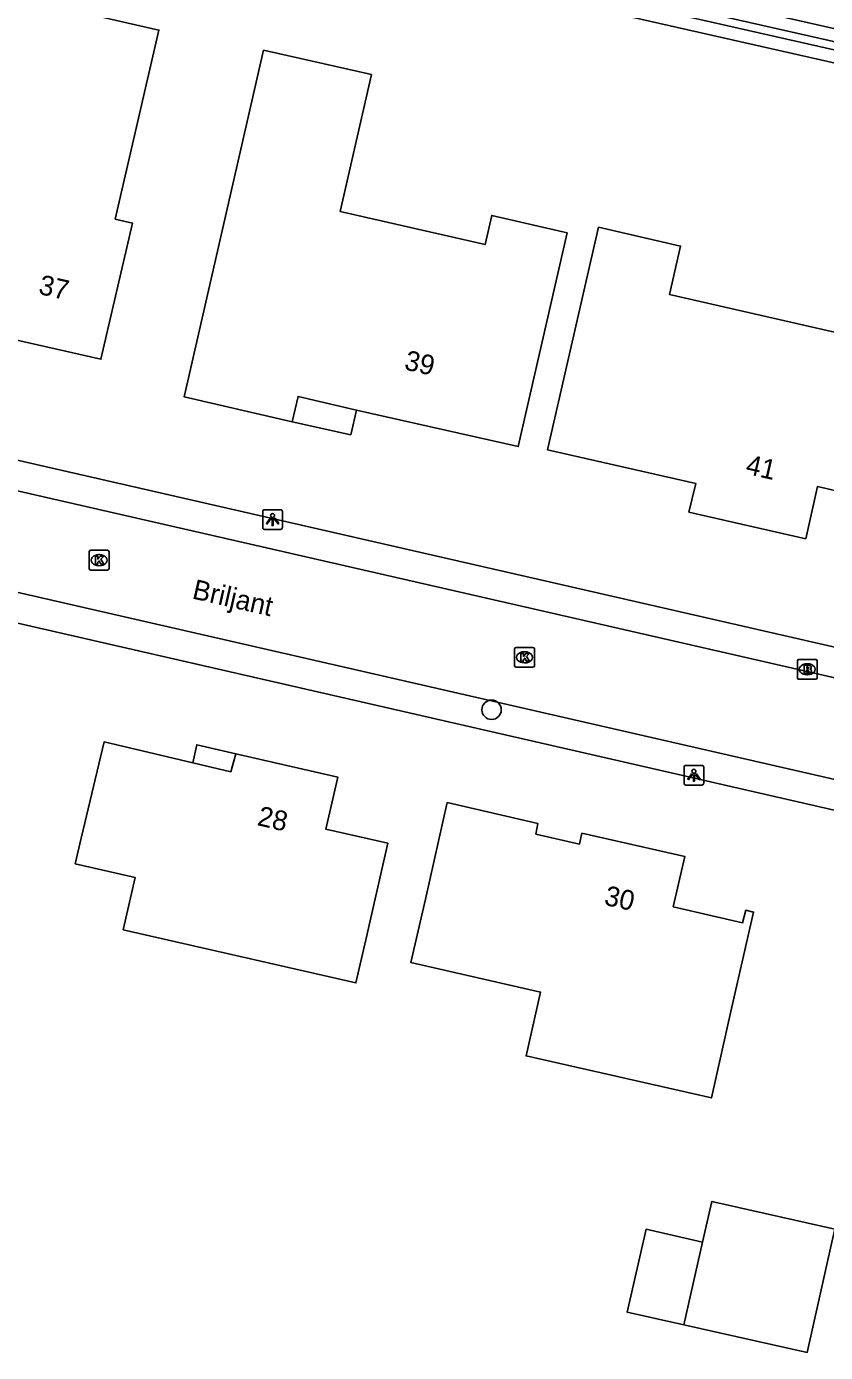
# Model space of a CAD drawing. Extents: x 159628 to 160723, y 388176 to 389416.
# Drawn here: x 160277.9 to 160318.3, y 388744.4 to 388811.4 of the extents above; entities that cross this region are included whole.
import ezdxf

# ---------------------------------------------------------------- set-up
doc = ezdxf.new("R2010")
doc.units = 0
for name, color, linetype in [('IMGEO_Boom', 7, 'Continuous'), ('IMGEO_Brandkraan', 7, 'Continuous'), ('IMGEO_Erf', 7, 'Continuous'), ('IMGEO_Groenvoorziening', 7, 'Continuous'), ('IMGEO_Kolk', 7, 'Continuous'), ('IMGEO_Lichtpunt', 7, 'Continuous'), ('IMGEO_Openbare_ruimte_label', 7, 'Continuous'), ('IMGEO_Pand', 7, 'Continuous'), ('IMGEO_Pand_nummerreeks', 7, 'Continuous'), ('IMGEO_Pand_overbouw', 7, 'Continuous'), ('IMGEO_Rijbaan_lokaal_open', 7, 'Continuous'), ('IMGEO_Voetpad_open', 7, 'Continuous'), ('IMGEO_Waterloop', 7, 'Continuous')]:
    doc.layers.add(name, color=color, linetype=linetype)

msp = doc.modelspace()

# ---------------------------------------------------------------- linework, layer by layer
at = {"layer": 'IMGEO_Boom'}
msp.add_circle((160301.407, 388776.893), 0.489, dxfattribs=at)
at = {"layer": 'IMGEO_Brandkraan'}
for p, q in [((160316.845, 388778.511), (160316.845, 388779.363)), ((160316.92, 388779.437), (160317.772, 388779.437)), ((160317.333, 388779.217), (160317.358, 388779.217)), ((160317.846, 388779.363), (160317.846, 388778.511)), ((160317.356, 388778.657), (160317.331, 388778.657)), ((160317.772, 388778.437), (160316.92, 388778.437))]:
    msp.add_line(p, q, dxfattribs=at)
for points in [[(160316.845, 388778.511), (160316.845, 388779.363)], [(160316.92, 388779.437), (160317.772, 388779.437)], [(160317.846, 388779.363), (160317.846, 388778.511)], [(160317.193, 388779.137), (160317.193, 388778.737), (160317.406, 388778.737)], [(160317.424, 388779.137), (160317.193, 388779.137)], [(160317.372, 388779.056), (160317.318, 388779.056), (160317.318, 388778.98)], [(160317.318, 388778.98), (160317.371, 388778.98)], [(160317.38, 388778.904), (160317.318, 388778.904), (160317.318, 388778.823)], [(160317.318, 388778.823), (160317.38, 388778.823)], [(160317.772, 388778.437), (160316.92, 388778.437)]]:
    msp.add_lwpolyline(points, dxfattribs=at)
for centre, radius, start, end in [((160316.922, 388779.361), 0.0765, 91.55205, 178.44795), ((160316.922, 388779.361), 0.0765, 91.55205, 178.44795), ((160317.77, 388779.361), 0.0765, 1.55205, 88.44795), ((160317.77, 388779.361), 0.0765, 1.55205, 88.44795), ((160316.922, 388778.513), 0.0765, 181.55205, 268.44795), ((160316.922, 388778.513), 0.0765, 181.55205, 268.44795), ((160317.373, 388779.018), 0.0379, 267.82845, 90.93552), ((160317.381, 388778.863), 0.0404, 269.87594, 90.50774), ((160317.412, 388778.988), 0.251, 268.66757, 293.53466), ((160317.428, 388778.992), 0.145, 59.4692, 91.53667), ((160317.453, 388779.039), 0.0922, 285.51372, 58.15012), ((160317.458, 388778.847), 0.105, 301.31148, 78.98903), ((160317.77, 388778.513), 0.0765, 271.55205, 358.44795), ((160317.77, 388778.513), 0.0765, 271.55205, 358.44795)]:
    msp.add_arc(centre, radius, start, end, dxfattribs=at)
for centre, major_axis, ratio, start_param, end_param in [((160317.332, 388778.937), (-0.387, 0.002), 0.722429, 4.712389, 7.853982), ((160317.357, 388778.937), (-0.39, 0.002), 0.717154, 1.570796, 4.712389)]:
    msp.add_ellipse(centre, major_axis=major_axis, ratio=ratio, start_param=start_param, end_param=end_param, dxfattribs=at)
at = {"layer": 'IMGEO_Erf'}
msp.add_lwpolyline([(160184.451, 388841.51), (160190.942, 388838.493), (160275.805, 388819.285), (160345.403, 388803.532)], dxfattribs=at)
at = {"layer": 'IMGEO_Groenvoorziening'}
msp.add_lwpolyline([(160345.403, 388803.532), (160345.702, 388804.941), (160343.204, 388805.76), (160276.177, 388820.926), (160191.577, 388840.068), (160187.273, 388842.53), (160192.324, 388844.405), (160277.11, 388825.048), (160331.448, 388812.643), (160346.394, 388809.56)], dxfattribs=at)
at = {"layer": 'IMGEO_Kolk'}
for p, q in [((160281.091, 388784.022), (160281.091, 388784.874)), ((160281.166, 388784.948), (160282.018, 388784.948)), ((160281.579, 388784.728), (160281.604, 388784.728)), ((160282.092, 388784.874), (160282.092, 388784.022)), ((160282.018, 388783.948), (160281.166, 388783.948)), ((160281.602, 388784.168), (160281.577, 388784.168)), ((160302.571, 388779.116), (160302.571, 388779.968)), ((160302.646, 388780.042), (160303.498, 388780.042)), ((160303.572, 388779.968), (160303.572, 388779.116)), ((160303.082, 388779.262), (160303.057, 388779.262)), ((160303.059, 388779.822), (160303.084, 388779.822)), ((160303.498, 388779.042), (160302.646, 388779.042))]:
    msp.add_line(p, q, dxfattribs=at)
for points in [[(160281.091, 388784.022), (160281.091, 388784.874)], [(160281.166, 388784.948), (160282.018, 388784.948)], [(160281.412, 388784.648), (160281.535, 388784.648), (160281.535, 388784.497), (160281.665, 388784.648), (160281.829, 388784.648), (160281.683, 388784.497), (160281.836, 388784.248), (160281.684, 388784.248), (160281.599, 388784.412), (160281.535, 388784.345), (160281.535, 388784.248), (160281.412, 388784.248), (160281.412, 388784.648)], [(160282.092, 388784.874), (160282.092, 388784.022)], [(160282.018, 388783.948), (160281.166, 388783.948)], [(160302.571, 388779.116), (160302.571, 388779.968)], [(160302.646, 388780.042), (160303.498, 388780.042)], [(160303.572, 388779.968), (160303.572, 388779.116)], [(160302.892, 388779.742), (160303.015, 388779.742), (160303.015, 388779.591), (160303.145, 388779.742), (160303.309, 388779.742), (160303.163, 388779.591), (160303.316, 388779.342), (160303.164, 388779.342), (160303.079, 388779.506), (160303.015, 388779.439), (160303.015, 388779.342), (160302.892, 388779.342), (160302.892, 388779.742)], [(160303.498, 388779.042), (160302.646, 388779.042)]]:
    msp.add_lwpolyline(points, dxfattribs=at)
for centre, start, end in [((160281.168, 388784.872), 91.55205, 178.44795), ((160281.168, 388784.872), 91.55205, 178.44795), ((160282.016, 388784.872), 1.55205, 88.44795), ((160282.016, 388784.872), 1.55205, 88.44795), ((160281.168, 388784.024), 181.55205, 268.44795), ((160281.168, 388784.024), 181.55205, 268.44795), ((160282.016, 388784.024), 271.55205, 358.44795), ((160282.016, 388784.024), 271.55205, 358.44795), ((160302.648, 388779.966), 91.55205, 178.44795), ((160302.648, 388779.966), 91.55205, 178.44795), ((160303.496, 388779.966), 1.55205, 88.44795), ((160303.496, 388779.966), 1.55205, 88.44795), ((160302.648, 388779.118), 181.55205, 268.44795), ((160302.648, 388779.118), 181.55205, 268.44795), ((160303.496, 388779.118), 271.55205, 358.44795), ((160303.496, 388779.118), 271.55205, 358.44795)]:
    msp.add_arc(centre, 0.0765, start, end, dxfattribs=at)
for centre, major_axis, ratio, start_param, end_param in [((160281.578, 388784.448), (-0.387, 0.002), 0.722429, 4.712389, 7.853982), ((160281.603, 388784.448), (-0.39, 0.002), 0.717154, 1.570796, 4.712389), ((160303.058, 388779.542), (-0.387, 0.002), 0.722429, 4.712389, 7.853982), ((160303.083, 388779.542), (-0.39, 0.002), 0.717154, 1.570796, 4.712389)]:
    msp.add_ellipse(centre, major_axis=major_axis, ratio=ratio, start_param=start_param, end_param=end_param, dxfattribs=at)
at = {"layer": 'IMGEO_Lichtpunt'}
for p, q in [((160289.852, 388786.904), (160289.852, 388786.097)), ((160289.852, 388786.904), (160289.852, 388786.097)), ((160290.754, 388786.999), (160289.946, 388786.999)), ((160290.754, 388786.999), (160289.946, 388786.999)), ((160290.848, 388786.097), (160290.848, 388786.904)), ((160290.848, 388786.097), (160290.848, 388786.904)), ((160289.946, 388786.003), (160290.754, 388786.003)), ((160289.946, 388786.003), (160290.754, 388786.003)), ((160311.123, 388773.987), (160311.123, 388773.18)), ((160311.123, 388773.987), (160311.123, 388773.18)), ((160312.025, 388774.082), (160311.217, 388774.082)), ((160312.025, 388774.082), (160311.217, 388774.082)), ((160312.119, 388773.18), (160312.119, 388773.987)), ((160312.119, 388773.18), (160312.119, 388773.987)), ((160311.217, 388773.086), (160312.025, 388773.086)), ((160311.217, 388773.086), (160312.025, 388773.086))]:
    msp.add_line(p, q, dxfattribs=at)
for points in [[(160290.226, 388786.568), (160290.265, 388786.54), (160290.077, 388786.278), (160290.039, 388786.305), (160290.226, 388786.568)], [(160290.438, 388786.54), (160290.476, 388786.567), (160290.663, 388786.305), (160290.624, 388786.277), (160290.438, 388786.54)], [(160290.328, 388786.52), (160290.375, 388786.52), (160290.375, 388786.198), (160290.328, 388786.198), (160290.328, 388786.52)], [(160311.497, 388773.651), (160311.536, 388773.623), (160311.348, 388773.361), (160311.31, 388773.388), (160311.497, 388773.651)], [(160311.599, 388773.603), (160311.646, 388773.603), (160311.646, 388773.281), (160311.599, 388773.281), (160311.599, 388773.603)], [(160311.709, 388773.623), (160311.747, 388773.65), (160311.934, 388773.388), (160311.895, 388773.36), (160311.709, 388773.623)]]:
    msp.add_lwpolyline(points, dxfattribs=at)
for centre in [(160290.351, 388786.702), (160311.622, 388773.785)]:
    msp.add_circle(centre, 0.0994, dxfattribs=at)
for centre, start, end in [((160289.946, 388786.904), 90, 180), ((160289.946, 388786.904), 90, 180), ((160290.754, 388786.904), 0, 90), ((160290.754, 388786.904), 0, 90), ((160289.946, 388786.097), 180, 270), ((160289.946, 388786.097), 180, 270), ((160290.754, 388786.097), 270, 0), ((160290.754, 388786.097), 270, 360), ((160311.217, 388773.987), 90, 180), ((160311.217, 388773.987), 90, 180), ((160312.025, 388773.987), 0, 90), ((160312.025, 388773.987), 0, 90), ((160311.217, 388773.18), 180, 270), ((160311.217, 388773.18), 180, 270), ((160312.025, 388773.18), 270, 0), ((160312.025, 388773.18), 270, 360)]:
    msp.add_arc(centre, 0.0946, start, end, dxfattribs=at)
at = {"layer": 'IMGEO_Pand'}
for points in [[(160269.416, 388805.915), (160275.66, 388804.469), (160277.599, 388812.844), (160284.612, 388811.221), (160282.403, 388801.679), (160283.279, 388801.476), (160281.686, 388794.597), (160275.782, 388795.937), (160275.862, 388796.301), (160274.298, 388796.665), (160274.011, 388795.415), (160272.055, 388795.867), (160271.994, 388795.641), (160270.709, 388795.976), (160270.739, 388796.156), (160268.289, 388796.758), (160269.045, 388800.332), (160268.176, 388800.561), (160269.416, 388805.915)], [(160289.9, 388810.21), (160295.34, 388808.98), (160293.762, 388802.068), (160301.084, 388800.397), (160301.418, 388801.859), (160305.22, 388800.991), (160302.753, 388790.184), (160294.594, 388792.025), (160291.64, 388792.721), (160291.337, 388791.442), (160285.882, 388792.7), (160289.9, 388810.21)], [(160306.799, 388801.261), (160310.946, 388800.312), (160310.388, 388797.873), (160319.315, 388795.831), (160319.76, 388797.773), (160323.75, 388796.86), (160321.573, 388787.306), (160317.857, 388788.164), (160317.267, 388785.534), (160311.37, 388786.881), (160311.72, 388788.318), (160304.23, 388790.025), (160306.799, 388801.261)], [(160282.807, 388765.779), (160283.411, 388768.424), (160280.375, 388769.117), (160280.681, 388770.404), (160281.839, 388775.268), (160286.324, 388774.211), (160288.24, 388773.759), (160288.488, 388774.673), (160293.638, 388773.496), (160293.041, 388770.861), (160296.171, 388770.153), (160295.058, 388765.279), (160294.56, 388763.096), (160282.807, 388765.779)], [(160298.064, 388767.324), (160299.17, 388772.2), (160303.738, 388771.152), (160303.634, 388770.61), (160305.852, 388770.108), (160305.97, 388770.655), (160311.164, 388769.485), (160310.576, 388766.946), (160314.077, 388766.131), (160314.247, 388766.762), (160314.633, 388766.673), (160313.527, 388761.797), (160312.504, 388757.286), (160303.146, 388759.409), (160303.878, 388762.635), (160297.337, 388764.119), (160298.064, 388767.324)], [(160312.063, 388750), (160312.533, 388752.059), (160318.743, 388750.663), (160318.594, 388750), (160317.344, 388744.428), (160311.11, 388745.819)], [(160312.063, 388750), (160309.21, 388750.651), (160308.254, 388746.456), (160311.11, 388745.819)], [(160311.11, 388745.819), (160312.063, 388750)]]:
    msp.add_lwpolyline(points, dxfattribs=at)
at = {"layer": 'IMGEO_Pand_overbouw'}
for points in [[(160291.337, 388791.442), (160294.3, 388790.786), (160294.594, 388792.025), (160291.64, 388792.721)], [(160288.488, 388774.673), (160286.524, 388775.129), (160286.324, 388774.211), (160288.24, 388773.759)]]:
    msp.add_lwpolyline(points, close=True, dxfattribs=at)
at = {"layer": 'IMGEO_Rijbaan_lokaal_open'}
for points in [[(160273.762, 388788.79), (160333.234, 388775.183)], [(160332.119, 388770.308), (160272.649, 388783.925)]]:
    msp.add_lwpolyline(points, dxfattribs=at)
at = {"layer": 'IMGEO_Voetpad_open'}
for points in [[(160271.421, 388790.878), (160340.358, 388775.105)], [(160338.544, 388767.28), (160259.096, 388785.469)]]:
    msp.add_lwpolyline(points, dxfattribs=at)
at = {"layer": 'IMGEO_Waterloop'}
msp.add_lwpolyline([(160178.075, 388845.483), (160184.732, 388842.086), (160191.15, 388839.103), (160275.947, 388819.91), (160344.911, 388804.301), (160344.955, 388804.511), (160343.033, 388805.141), (160276.036, 388820.301), (160191.342, 388839.464), (160185.765, 388842.654), (160191.84, 388844.909), (160346.24, 388809.831), (160346.351, 388809.852), (160346.376, 388809.865)], dxfattribs=at)

# ---------------------------------------------------------------- texts
at = {"layer": 'IMGEO_Openbare_ruimte_label'}
msp.add_text('Briljant', height=1, rotation=347.11702, dxfattribs=at).set_placement((160286.245, 388782.521))
at = {"layer": 'IMGEO_Pand_nummerreeks'}
for s, rotation, p in [('37', 347.21251, (160278.486, 388797.907)), ('39', 347.14026, (160296.952, 388794.093)), ('41', 347.13318, (160314.184, 388788.823)), ('28', 347.12651, (160289.53, 388771.07)), ('30', 347.30544, (160307.044, 388767.051))]:
    msp.add_text(s, height=1, rotation=rotation, dxfattribs=at).set_placement(p)

doc.saveas('drawing.dxf')
